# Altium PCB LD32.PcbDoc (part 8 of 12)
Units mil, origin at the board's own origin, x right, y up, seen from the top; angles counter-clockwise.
Board outline 7007.87 x 4368.85 mil, 12 copper layers (Top Layer, Int1 (GND), Int2 (AVDD), Int3 (DVDD), Int4 (GND), Int5 (ST), Int6 (SB), Int8 (AGND), Int7 (AVCC), Int9 (VCCA), Int10 (GND), Bottom Layer), stack 60.136 mil thick; 1165 components, 667 nets, 3910 pads, 2570 vias.
Unrouted connection lines stored in the file: 14.
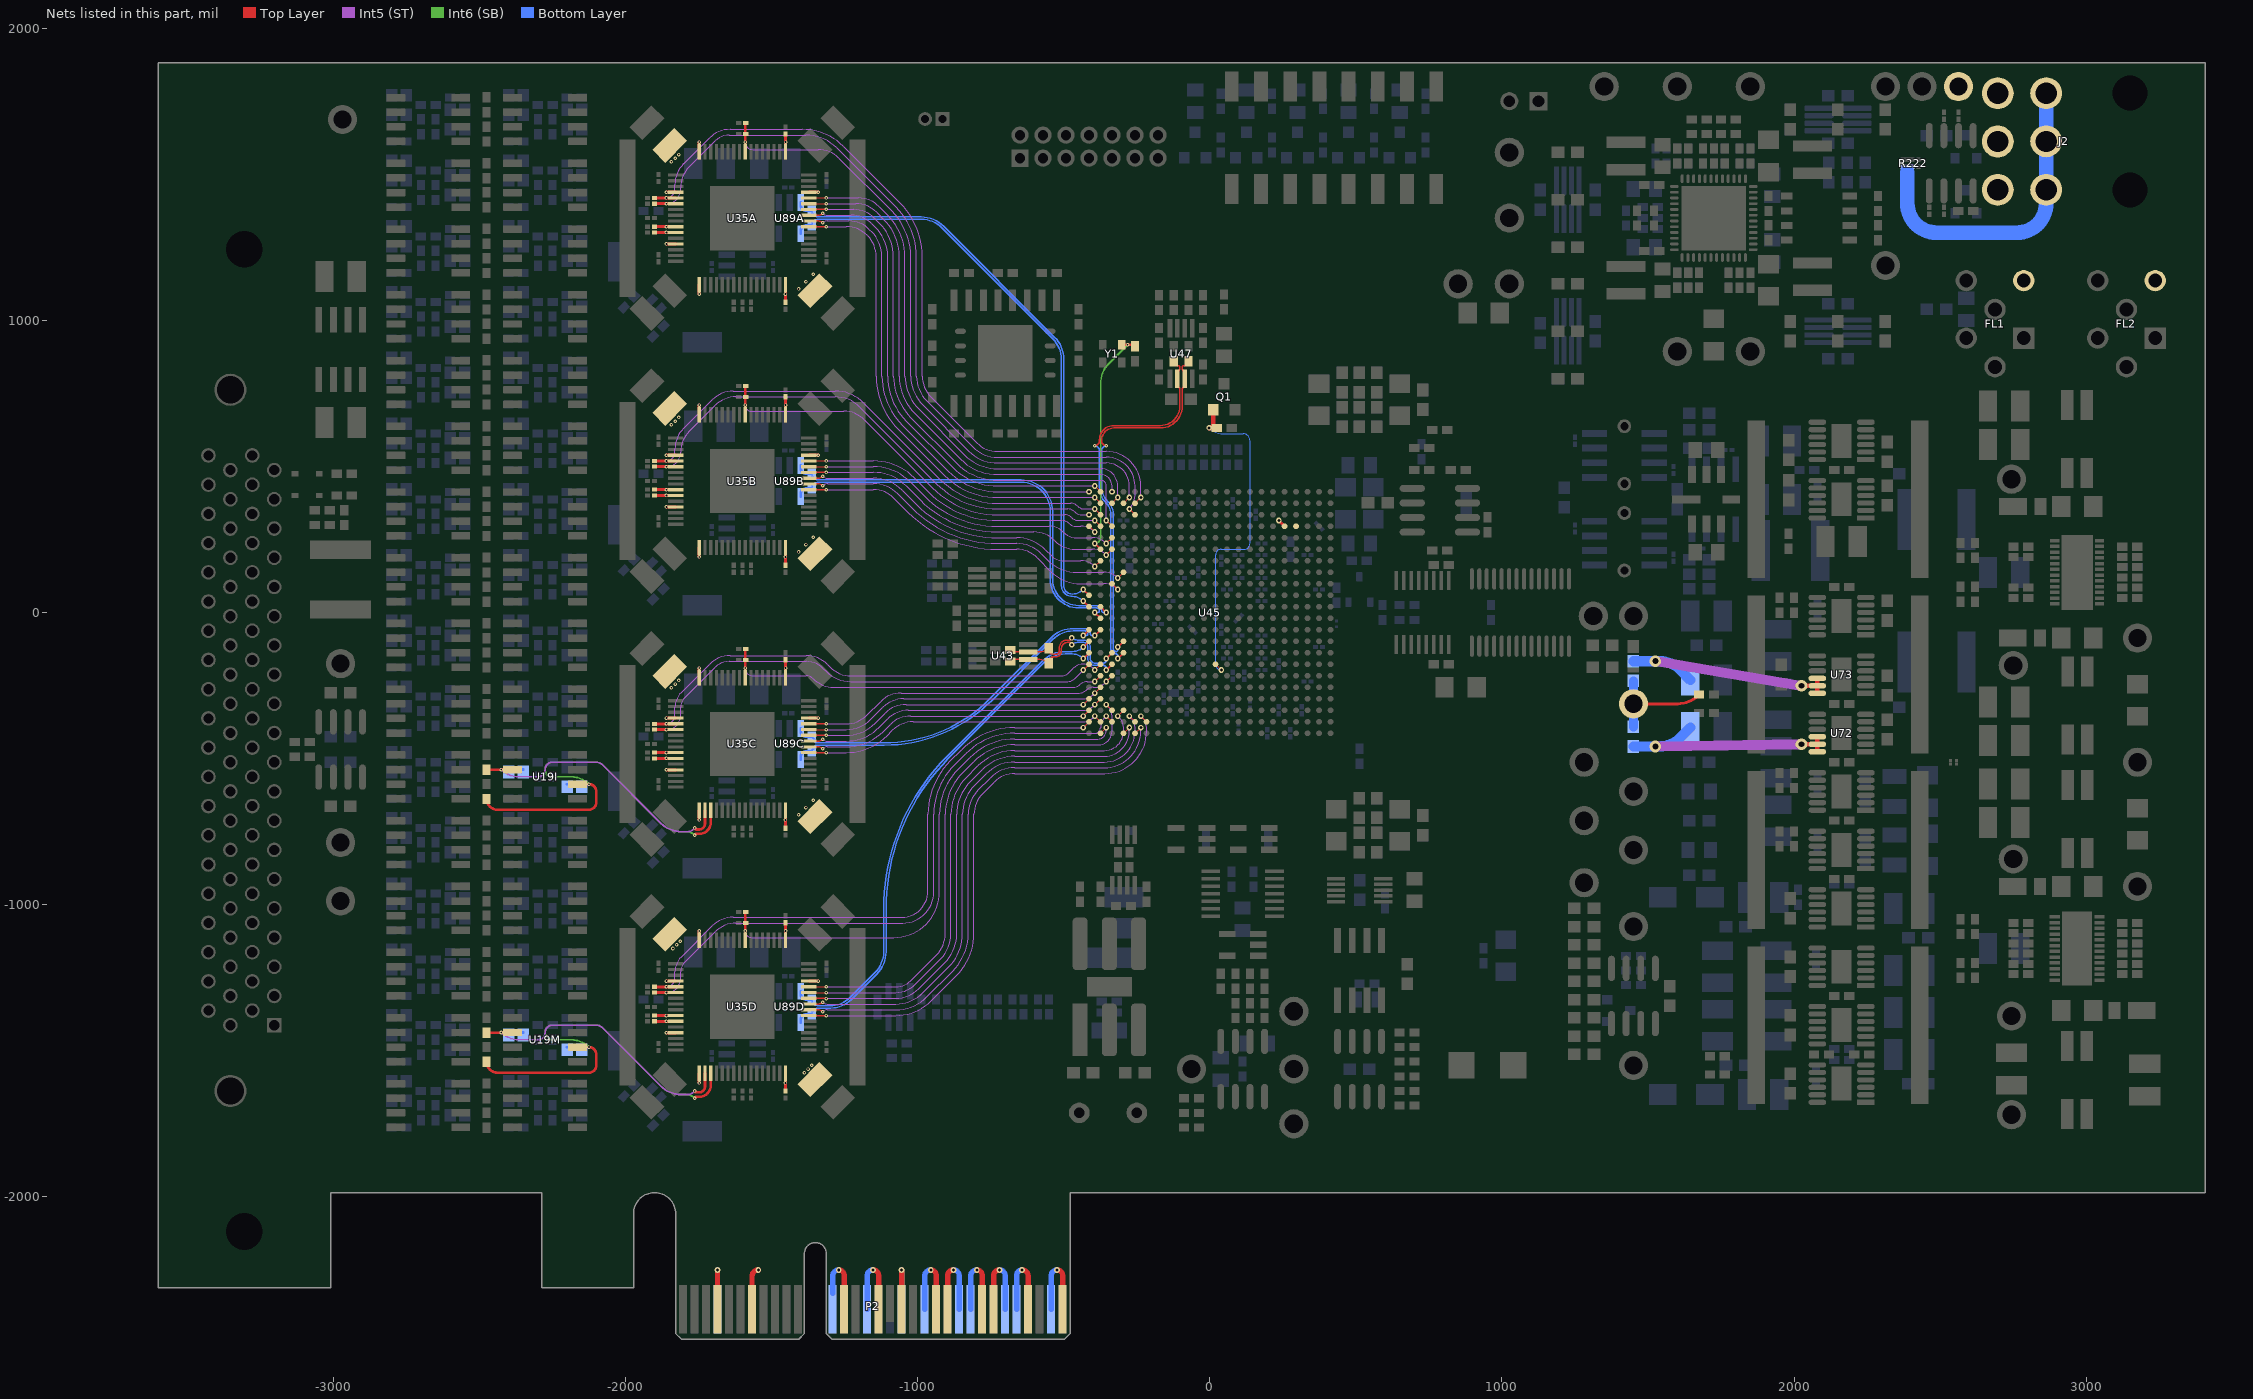
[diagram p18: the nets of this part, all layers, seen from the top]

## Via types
v1: diameter 12, hole 6, Top Layer to Bottom Layer, tented both sides, 1500 vias
v2: diameter 19, hole 10, Top Layer to Bottom Layer, tented both sides, 404 vias
v3: diameter 20, hole 10, Top Layer to Bottom Layer, tented both sides, 337 vias
v4: diameter 14, hole 7, Top Layer to Bottom Layer, tented both sides, 212 vias
v5: diameter 30, hole 15, Top Layer to Bottom Layer, tented both sides, 37 vias
v6: diameter 19.68, hole 7.87, Top Layer to Bottom Layer, 25 vias
v7: diameter 40, hole 20, Top Layer to Bottom Layer, tented both sides, 16 vias
v8: diameter 19.02, hole 10, Top Layer to Bottom Layer, tented both sides, 10 vias
v9: diameter 40, hole 20, Top Layer to Bottom Layer, 9 vias
v10: diameter 60, hole 40, Top Layer to Bottom Layer, 5 vias
v11: diameter 25, hole 13, Top Layer to Bottom Layer, 4 vias
v12: diameter 50, hole 25, Top Layer to Bottom Layer, tented both sides, 4 vias
v13: diameter 35, hole 20, Top Layer to Bottom Layer, 2 vias
v14: diameter 50, hole 25, Top Layer to Bottom Layer, 2 vias
v15: diameter 63, hole 45, Top Layer to Bottom Layer, 1 vias
v16: diameter 14.02, hole 7.01, Top Layer to Bottom Layer, tented both sides, 1 vias
v17: diameter 60, hole 40, Top Layer to Bottom Layer, tented both sides, 1 vias

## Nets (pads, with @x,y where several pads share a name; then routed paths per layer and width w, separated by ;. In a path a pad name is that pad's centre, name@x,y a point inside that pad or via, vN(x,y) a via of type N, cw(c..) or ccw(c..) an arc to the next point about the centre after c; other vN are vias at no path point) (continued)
D8C_N: C319I.2 R7I.2 R335I.1 U19I.6 U35C.35 | length 3191.3
  Top Layer w9: U19I.6@-2163.78,-587.5 v1(-2125,-587.5) ; -2100,-649.92 cw(c-2125,-649.92) -2125,-674.92 -2438.09,-674.92 -2438.09,-675 ; v1(-1762.5,-762.5) cw(c-1757.5,-762.5) -1757.5,-757.5 -1747.5,-757.5 ccw(c-1747.5,-718.27) -1708.27,-718.27 U35C.35@-1708.27,-677.5 ; R7I.2@-2475,-638.09 ccw(c-2438.09,-638.09) -2438.09,-675 ; R7I.2@-2475,-638.09 ccw(c-2438.09,-638.09) -2438.09,-675 ; R7I.2@-2475,-638.09 ccw(c-2438.09,-638.09) -2438.09,-675 ; R7I.2@-2475,-638.09 ccw(c-2438.09,-638.09) -2438.09,-675 ; R7I.2@-2475,-638.09 ccw(c-2438.09,-638.09) -2438.09,-675 ; -2125,-675 ccw(c-2125,-650) -2100,-650 ; -2125,-675 ccw(c-2125,-650) -2100,-650 ; -2125,-675 ccw(c-2125,-650) -2100,-650 ; -2125,-675 ccw(c-2125,-650) -2100,-650 ; -2125,-675 ccw(c-2125,-650) -2100,-650 ; -2125,-675 ccw(c-2125,-650) -2100,-650 ; -2125,-675 ccw(c-2125,-650) -2100,-650 ; -2125,-675 ccw(c-2125,-650) -2100,-650 ; -2125,-675 ccw(c-2125,-650) -2100,-650 ; -2125,-675 ccw(c-2125,-650) -2100,-650 ; -2125,-675 ccw(c-2125,-650) -2100,-650 ; -2125,-675 ccw(c-2125,-650) -2100,-650 ; -2125,-675 ccw(c-2125,-650) -2100,-650 ; -2125,-675 ccw(c-2125,-650) -2100,-650 ; -2125,-675 ccw(c-2125,-650) -2100,-650 ; -2125,-675 ccw(c-2125,-650) -2100,-650 ; -2125,-675 ccw(c-2125,-650) -2100,-650 ; -2125,-675 ccw(c-2125,-650) -2100,-650 ; -2125,-675 ccw(c-2125,-650) -2100,-650 ; -2125,-675 ccw(c-2125,-650) -2100,-650 ; -2125,-675 ccw(c-2125,-650) -2100,-650 ; v1(-2125,-587.5) cw(c-2125,-612.5) -2100,-612.5 ; v1(-2125,-587.5) cw(c-2125,-612.5) -2100,-612.5 ; v1(-2125,-587.5) cw(c-2125,-612.5) -2100,-612.5 ; v1(-2125,-587.5) cw(c-2125,-612.5) -2100,-612.5 ; v1(-2125,-587.5) cw(c-2125,-612.5) -2100,-612.5 ; v1(-2125,-587.5) cw(c-2125,-612.5) -2100,-612.5 ; v1(-2125,-587.5) cw(c-2125,-612.5) -2100,-612.5 ; v1(-2125,-587.5) cw(c-2125,-612.5) -2100,-612.5 ; v1(-2125,-587.5) cw(c-2125,-612.5) -2100,-612.5 ; v1(-2125,-587.5) cw(c-2125,-612.5) -2100,-612.5 ; v1(-2125,-587.5) cw(c-2125,-612.5) -2100,-612.5 ; v1(-2125,-587.5) cw(c-2125,-612.5) -2100,-612.5 ; -2100,-650 -2100,-612.5 ; -2100,-650 -2100,-612.5
  Int6 (SB) w6: v1(-2125,-587.5) ccw(c-2185.36,-647.86) -2185.36,-562.5 -2250,-562.5 cw(c-2250,-537.5) -2275,-537.5 cw(c-2250,-537.5) -2250,-512.5 ; -1792.5,-750 -1792.68,-750 ; v1(-1762.5,-762.5) ccw(c-1792.68,-792.68) -1792.68,-750 ; -2250,-512.5 -2100,-512.5 ; -2250,-512.5 -2100,-512.5 ; -2100,-512.5 cw(c-2100,-542.68) -2078.66,-521.34 -1879.29,-720.71 ccw(c-1808.58,-650) -1808.58,-750 -1792.68,-750
  Bottom Layer w9: R335I.1@-2200,-587.5 v1(-2125,-587.5)
D8C_P: C383I.2 R8I.2 R383I.1 U19I.2 U35C.34 | length 1808.4
  Top Layer w9: R8I.2@-2475,-538.09 v1(-2425,-537.5) U19I.2@-2386.22,-537.5 U19I.2@-2380,-537.5 ; v1(-1762.5,-737.5) ccw(c-1757.5,-737.5) -1757.5,-742.5 -1747.5,-742.5 ccw(c-1747.5,-722.95) -1727.95,-722.95 U35C.34@-1727.95,-677.5
  Int5 (ST) w6: v1(-2425,-537.5) ccw(c-2364.64,-477.14) -2364.64,-562.5 -2300,-562.5 ccw(c-2300,-537.5) -2275,-537.5 cw(c-2250,-537.5) -2250,-512.5 ; v1(-1762.5,-737.5) -1766.16,-741.16 cw(c-1787.5,-719.82) -1787.5,-750 -1808.58,-750 cw(c-1808.58,-650) -1879.29,-720.71 -2078.66,-521.34 ccw(c-2100,-542.68) -2100,-512.5 ; -2250,-512.5 -2100,-512.5 ; -2250,-512.5 -2100,-512.5 ; -2250,-512.5 -2100,-512.5 ; -2250,-512.5 -2100,-512.5 ; -2250,-512.5 -2100,-512.5 ; -2250,-512.5 -2100,-512.5
  Bottom Layer w9: v1(-2425,-537.5) R383I.1@-2350,-537.5
D8D_N: C319M.2 R7M.2 R335M.1 U19M.6 U35D.35 | length 2602.1
  Top Layer w9: U19M.6@-2163.78,-1487.5 v1(-2125,-1487.5) ; v1(-1762.5,-1662.5) cw(c-1757.5,-1662.5) -1757.5,-1657.5 -1747.5,-1657.5 ccw(c-1747.5,-1618.27) -1708.27,-1618.27 U35D.35@-1708.27,-1577.5 ; R7M.2@-2475,-1538.09 ccw(c-2438.09,-1538.09) -2438.09,-1575 ; R7M.2@-2475,-1538.09 ccw(c-2438.09,-1538.09) -2438.09,-1575 ; R7M.2@-2475,-1538.09 ccw(c-2438.09,-1538.09) -2438.09,-1575 ; R7M.2@-2475,-1538.09 ccw(c-2438.09,-1538.09) -2438.09,-1575 ; R7M.2@-2475,-1538.09 ccw(c-2438.09,-1538.09) -2438.09,-1575 ; -2438.09,-1575 -2125,-1575 ; -2125,-1575 ccw(c-2125,-1550) -2100,-1550 ; -2125,-1575 ccw(c-2125,-1550) -2100,-1550 ; -2125,-1575 ccw(c-2125,-1550) -2100,-1550 ; -2125,-1575 ccw(c-2125,-1550) -2100,-1550 ; -2125,-1575 ccw(c-2125,-1550) -2100,-1550 ; -2125,-1575 ccw(c-2125,-1550) -2100,-1550 ; -2125,-1575 ccw(c-2125,-1550) -2100,-1550 ; -2125,-1575 ccw(c-2125,-1550) -2100,-1550 ; -2125,-1575 ccw(c-2125,-1550) -2100,-1550 ; -2125,-1575 ccw(c-2125,-1550) -2100,-1550 ; -2125,-1575 ccw(c-2125,-1550) -2100,-1550 ; -2125,-1575 ccw(c-2125,-1550) -2100,-1550 ; v1(-2125,-1487.5) cw(c-2125,-1512.5) -2100,-1512.5 ; v1(-2125,-1487.5) cw(c-2125,-1512.5) -2100,-1512.5 ; v1(-2125,-1487.5) cw(c-2125,-1512.5) -2100,-1512.5 ; v1(-2125,-1487.5) cw(c-2125,-1512.5) -2100,-1512.5 ; v1(-2125,-1487.5) cw(c-2125,-1512.5) -2100,-1512.5 ; v1(-2125,-1487.5) cw(c-2125,-1512.5) -2100,-1512.5 ; v1(-2125,-1487.5) cw(c-2125,-1512.5) -2100,-1512.5 ; -2100,-1550 -2100,-1512.5 ; -2100,-1550 -2100,-1512.5
  Int6 (SB) w6: v1(-2125,-1487.5) ccw(c-2185.36,-1547.86) -2185.36,-1462.5 -2250,-1462.5 cw(c-2250,-1437.5) -2275,-1437.5 cw(c-2250,-1437.5) -2250,-1412.5 ; -1792.5,-1650 -1792.68,-1650 ; v1(-1762.5,-1662.5) ccw(c-1792.68,-1692.68) -1792.68,-1650 ; -2250,-1412.5 -2100,-1412.5 ; -2250,-1412.5 -2100,-1412.5 ; -2100,-1412.5 cw(c-2100,-1442.68) -2078.66,-1421.34 -1879.29,-1620.71 ccw(c-1808.58,-1550) -1808.58,-1650 -1792.68,-1650
  Bottom Layer w9: R335M.1@-2200,-1487.5 v1(-2125,-1487.5)
D8D_P: C383M.2 R8M.2 R383M.1 U19M.2 U35D.34 | length 1508.4
  Top Layer w9: R8M.2@-2475,-1438.09 v1(-2425,-1437.5) U19M.2@-2386.22,-1437.5 U19M.2@-2380,-1437.5 ; v1(-1762.5,-1637.5) ccw(c-1757.5,-1637.5) -1757.5,-1642.5 -1747.5,-1642.5 ccw(c-1747.5,-1622.95) -1727.95,-1622.95 U35D.34@-1727.95,-1577.5
  Int5 (ST) w6: v1(-2425,-1437.5) ccw(c-2364.64,-1377.14) -2364.64,-1462.5 -2300,-1462.5 ccw(c-2300,-1437.5) -2275,-1437.5 cw(c-2250,-1437.5) -2250,-1412.5 ; v1(-1762.5,-1637.5) -1766.16,-1641.16 cw(c-1787.5,-1619.82) -1787.5,-1650 -1808.58,-1650 cw(c-1808.58,-1550) -1879.29,-1620.71 -2078.66,-1421.34 ccw(c-2100,-1442.68) -2100,-1412.5 ; -2250,-1412.5 -2100,-1412.5 ; -2250,-1412.5 -2100,-1412.5 ; -2250,-1412.5 -2100,-1412.5 ; -2250,-1412.5 -2100,-1412.5
  Bottom Layer w9: v1(-2425,-1437.5) R383M.1@-2350,-1437.5
DAC1.BCLK: U35A.60 U45.AA20 | length 1842.3
  Top Layer w4.2: U35A.60@-1372.5,1418.9 v1(-1312.5,1418.9)
  Top Layer w4.21: U45.AA20@-334.65,374.02 v2(-314.96,393.7)
  Int5 (ST) w4.21: v1(-1312.5,1418.9) -1312.35,1418.75 -1202.87,1418.75 cw(c-1202.87,1318.75) -1132.16,1389.46 -1101.42,1358.73 cw(c-1241.73,1218.42) -1043.31,1218.42 -1043.31,809.14 ccw(c-884.25,809.14) -996.72,696.67 -838.76,538.71 ccw(c-726.3,651.18) -726.3,492.13 -374.02,492.13 cw(c-374.02,433.07) -314.96,433.07 v2(-314.96,393.7)
DAC1.D0: U35A.58 U45.W20 | length 1867.1
  Top Layer w4.21: v2(-354.33,314.96) U45.W20@-334.65,295.28
  Top Layer w5: U35A.58@-1372.5,1379.53 -1372.09,1379.93 -1312.91,1379.93 v1(-1312.5,1380.34)
  Int5 (ST) w4.21: v1(-1312.5,1380.34) -1311.69,1379.53 -1219.32,1379.53 cw(c-1219.32,1279.53) -1148.61,1350.24 -1129.26,1330.89 cw(c-1241.73,1218.42) -1082.68,1218.42 -1082.68,1172.14 ; -1082.68,1181.1 -1082.68,1172.14 ; v2(-354.33,314.96) -354.33,433.07 ccw(c-374.02,433.07) -374.02,452.76 -726.3,452.76 cw(c-726.3,651.18) -866.6,510.87 -1024.56,668.83 cw(c-884.25,809.14) -1082.68,809.14 -1082.68,1172.14
DAC1.D1: U35A.57 U45.AB21 | length 1691.4
  Top Layer w4.21: v2(-393.7,433.07) U45.AB21@-374.02,413.39
  Top Layer w5: U35A.57@-1372.5,1359.84 -1340.47,1359.84 ccw(c-1340.47,1381.72) v1(-1325,1366.25)
  Int5 (ST) w4.21: v1(-1325,1366.25) ccw(c-1309.53,1381.72) -1309.53,1359.84 -1227.48,1359.84 cw(c-1227.48,1259.84) -1156.77,1330.55 -1143.18,1316.97 cw(c-1241.73,1218.42) -1102.36,1218.42 -1102.36,809.14 ccw(c-884.25,809.14) -1038.48,654.91 -880.52,496.95 ccw(c-726.3,651.18) -726.3,433.07 v2(-393.7,433.07)
DAC1.D2: U35A.56 U45.AB22 | length 1643
  Top Layer w5: U35A.56@-1372.5,1340.16 -1340.47,1340.16 cw(c-1340.47,1318.28) v1(-1325,1333.75)
  Int5 (ST) w4.21: v1(-1325,1333.75) cw(c-1309.53,1318.28) -1309.53,1340.16 -1235.63,1340.16 cw(c-1235.63,1240.16) -1164.92,1310.87 -1157.1,1303.05 cw(c-1241.73,1218.42) -1122.05,1218.42 -1122.05,809.14 ccw(c-884.25,809.14) -1052.4,640.99 -894.44,483.03 ccw(c-726.3,651.18) -726.3,413.39 v2(-413.39,413.39)
DAC1.D3: U35A.55 U45.AA21 | length 1686.2
  Top Layer w4.21: v2(-393.7,393.7) U45.AA21@-374.02,374.02
  Top Layer w5: U35A.55@-1372.5,1320.47 v1(-1312.5,1320.47)
  Int5 (ST) w4.21: v1(-1312.5,1320.47) -1243.78,1320.47 cw(c-1243.78,1220.47) -1173.07,1291.18 -1171.02,1289.13 cw(c-1241.73,1218.42) -1141.73,1218.42 -1141.73,809.14 ccw(c-884.25,809.14) -1066.32,627.07 -908.36,469.12 ccw(c-726.3,651.18) -726.3,393.7 v2(-393.7,393.7)
DAC1.DCLK_N: R319A.1 U45.M22 U89A.4 | length 2041.2
  Top Layer w5: v2(-433.07,39.37) U45.M22@-413.39,19.69
  Bottom Layer w5: R319A.1@-1362.5,1324.41 cw(c-1340.91,1324.41) -1340.91,1346 -987.42,1346 cw(c-987.42,1246) -916.71,1316.71 -537.29,937.29 cw(c-608,866.58) -508,866.58 -508,92.12 ccw(c-470.94,92.12) -470.94,55.06 cw(c-470.94,1.5) v2(-433.07,39.37)
  Bottom Layer w9: U89A.4@-1400.1,1296.85 -1400.1,1306.81 cw(c-1382.5,1306.81) -1382.5,1324.41 R319A.1@-1362.5,1324.41
DAC1.DCLK_P: R319A.2 U45.N22 U89A.3 | length 2041.2
  Top Layer w5: v2(-433.07,78.74) U45.N22@-413.39,59.06
  Bottom Layer w5: R319A.2@-1362.5,1375.59 ccw(c-1340.91,1375.59) -1340.91,1354 -987.42,1354 cw(c-987.42,1246) -911.05,1322.37 -531.63,942.95 cw(c-608,866.58) -500,866.58 -500,92.12 ccw(c-470.94,92.12) -470.94,63.06 ccw(c-470.94,116.61) v2(-433.07,78.74)
  Bottom Layer w9: U89A.3@-1400.1,1403.15 -1400.1,1393.19 ccw(c-1382.5,1393.19) -1382.5,1375.59 R319A.2@-1362.5,1375.59
DAC1.GPIO3: R40A.1 U35A.26 | length 64.3
  Top Layer w10: R40A.1@-1891.83,1320.47 v1(-1860,1320.47) U35A.26@-1827.5,1320.47
DAC1.GPIO4: R39A.1 U35A.27 | length 64.3
  Top Layer w10: R39A.1@-1891.83,1300.79 v1(-1860,1300.79) U35A.27@-1827.5,1300.79
DAC1.LRCK: U35A.59 U45.AB20 | length 1775
  Top Layer w4.21: U35A.59@-1372.5,1399.21 v1(-1312.5,1399.21)
  Int5 (ST) w4.21: v1(-1312.5,1399.21) -1211.17,1399.21 cw(c-1211.17,1299.21) -1140.46,1369.92 -1115.34,1344.81 cw(c-1241.73,1218.42) -1062.99,1218.42 -1062.99,1169.15 ; -1062.99,1181.1 -1062.99,1169.15 ; v2(-334.65,413.39) -334.65,433.07 ccw(c-374.02,433.07) -374.02,472.44 -726.3,472.44 cw(c-726.3,651.18) -852.68,524.79 -1010.64,682.75 cw(c-884.25,809.14) -1062.99,809.14 -1062.99,1169.15
DAC1.RST: R55A.2 R56A.1 U35A.8 U45.AA19 | length 2285.1
  Top Layer w4.21: U45.AA19@-295.28,374.02 v2(-275.59,393.7)
  Top Layer w9: U35A.8@-1590.16,1577.5 v1(-1590.16,1610) -1590.16,1611.36 -1590.16,1672.91 cw(c-1588.06,1672.91) R56A.1@-1588.06,1675
  Int5 (ST) w4.21: v1(-1590.16,1610) ccw(c-1564.8,1610) -1564.8,1584.65 -1340.92,1584.65 cw(c-1340.92,1484.65) -1270.21,1555.36 -1087.51,1372.65 cw(c-1241.73,1218.42) -1023.62,1218.42 -1023.62,809.14 ccw(c-884.25,809.14) -982.8,710.59 -824.84,552.63 ccw(c-726.3,651.18) -726.3,511.81 -354.33,511.81 cw(c-354.33,433.07) -275.59,433.07 v2(-275.59,393.7)
DAC1.SCL: R41A.1 U35A.22 U45.Y18 | length 2718.3
  Top Layer w4.21: v2(-275.59,354.33) U45.Y18@-255.91,334.65
  Top Layer w10: R41A.1@-1891.83,1399.21 v1(-1860,1399.21) U35A.22@-1827.5,1399.21
  Int5 (ST) w4.21: v1(-1860,1399.21) ccw(c-1860,1448.19) -1811.02,1448.19 -1811.02,1454.64 cw(c-1711.02,1454.64) -1781.73,1525.35 -1781.5,1525.59 -1692.91,1614.17 cw(c-1645.39,1566.65) -1645.39,1633.86 -1382.68,1633.86 cw(c-1382.68,1484.65) -1277.17,1590.15 -1073.59,1386.57 cw(c-1241.73,1218.42) -1003.94,1218.42 -1003.94,809.14 ccw(c-884.25,809.14) -968.88,724.51 -810.93,566.55 ccw(c-726.3,651.18) -726.3,531.5 -354.33,531.5 cw(c-354.33,433.07) -255.91,433.07 -255.91,401.85 cw(c-323.11,401.85) v2(-275.59,354.33)
DAC1.SDA: R42A.1 U35A.21 U45.AA18 | length 2704.6
  Top Layer w4.21: U45.AA18@-255.91,374.02 v2(-236.22,393.7)
  Top Layer w10: R42A.1@-1891.83,1418.9 v1(-1860,1418.9) U35A.21@-1827.5,1418.9
  Int5 (ST) w4.21: v1(-1860,1418.9) ccw(c-1860,1448.19) -1830.71,1448.19 -1830.71,1464.48 cw(c-1730.71,1464.48) -1801.42,1535.19 -1801.18,1535.43 -1722.44,1614.17 -1712.36,1624.25 cw(c-1641.65,1553.54) -1641.65,1653.54 -1394.91,1653.54 cw(c-1394.91,1455.12) -1254.6,1595.43 -1059.67,1400.49 cw(c-1241.73,1218.42) -984.25,1218.42 -984.25,1181.1 -984.25,809.14 ccw(c-884.25,809.14) -954.96,738.43 -797.01,580.47 ccw(c-726.3,651.18) -726.3,551.18 -354.33,551.18 cw(c-354.33,433.07) -236.22,433.07 v2(-236.22,393.7)
DAC2.BCLK: U35B.60 U45.W22 | length 1078.7
  Top Layer w4.2: U35B.60@-1372.5,518.9 v1(-1312.5,518.9)
  Top Layer w4.21: U45.W22@-413.39,295.28 v2(-393.7,275.59)
  Int5 (ST) w4.21: v1(-1312.5,518.9) -1312.35,518.75 -1151.24,518.75 cw(c-1151.24,321.06) -1011.45,460.85 -964.04,413.44 ccw(c-726.3,651.18) -726.3,314.96 -506.09,314.96 -506.03,314.96 cw(c-506.05,281.36) -482.29,305.12 ccw(c-458.52,328.88) -458.52,295.28 -441.22,295.28 cw(c-441.22,228.07) v2(-393.7,275.59)
DAC2.D0: U35B.58 U45.U20 | length 1128.6
  Top Layer w4.21: v2(-354.33,196.85) U45.U20@-334.65,216.54
  Top Layer w5: U35B.58@-1372.5,479.53 v1(-1312.5,479.53)
  Int5 (ST) w4.21: v1(-1312.5,479.53) -1151.51,479.53 cw(c-1151.51,320.92) -1039.35,433.07 -991.88,385.6 ccw(c-726.3,651.18) -726.3,275.59 -602.23,275.59 -602.11,275.59 cw(c-602.11,176.41) -531.5,246.06 ccw(c-460.21,317.35) -460.21,216.54 ; -460.18,216.54 -401.85,216.54 cw(c-401.85,149.33) v2(-354.33,196.85)
DAC2.D1: U35B.57 U45.T21 | length 1100.8
  Top Layer w4.21: v2(-393.7,157.48) U45.T21@-374.02,177.17
  Top Layer w5: U35B.57@-1372.5,459.84 -1340.47,459.84 ccw(c-1340.47,481.72) v1(-1325,466.25)
  Int5 (ST) w4.21: v1(-1325,466.25) ccw(c-1309.53,481.72) -1309.53,459.84 -1151.57,459.84 cw(c-1151.57,320.77) -1053.23,419.11 -1005.8,371.68 ccw(c-726.3,651.18) -726.3,255.91 -661.5,255.91 cw(c-661.5,116.54) -562.95,215.08 -543.03,195.16 ccw(c-499.58,238.61) -499.58,177.17 -441.22,177.17 cw(c-441.22,109.96) v2(-393.7,157.48)
DAC2.D2: U35B.56 U45.R19 | length 1185.7
  Top Layer w4.21: v2(-314.96,118.11) U45.R19@-295.28,137.8
  Top Layer w5: U35B.56@-1372.5,440.16 -1340.47,440.16 cw(c-1340.47,418.28) v1(-1325,433.75)
  Int5 (ST) w4.21: v1(-1325,433.75) cw(c-1307.63,416.38) -1307.63,440.94 -1152.42,440.94 cw(c-1152.42,321.41) -1067.89,405.93 -1019.72,357.76 ccw(c-726.3,651.18) -726.3,236.22 -661.5,236.22 cw(c-661.5,116.54) -576.87,201.17 -554.32,178.62 ccw(c-455.77,277.17) -455.77,137.8 -362.48,137.8 cw(c-362.48,70.59) v2(-314.96,118.11)
DAC2.D3: U35B.55 U45.P20 | length 1190.6
  Top Layer w4.21: U45.P20@-334.65,98.43 v2(-314.96,78.74)
  Top Layer w5: U35B.55@-1372.5,420.47 v1(-1312.5,420.47)
  Int5 (ST) w4.21: v1(-1312.5,420.47) -1151.69,420.47 cw(c-1151.69,320.47) -1080.98,391.18 -1033.64,343.84 ccw(c-726.3,651.18) -726.3,216.54 -661.5,216.54 cw(c-661.5,116.54) -590.79,187.25 -543.73,140.18 ccw(c-442.91,241) -442.91,98.43 -362.48,98.43 cw(c-362.48,31.22) v2(-314.96,78.74)
DAC2.DCLK_N: R319B.1 U45.L21 U89B.4 | length 1452.5
  Top Layer w5: v2(-393.7,0) U45.L21@-374.02,-19.68
  Bottom Layer w5: R319B.1@-1362.5,424.41 cw(c-1340.91,424.41) -1340.91,446 -645.85,446 cw(c-645.85,346) -545.85,346 -545.85,113.05 ccw(c-448.55,113.05) -448.55,15.75 -387.86,15.75 cw(c-387.86,5.91) -378.02,5.91 cw(c-383.92,5.91) -383.92,0 v2(-393.7,0)
  Bottom Layer w9: U89B.4@-1400.1,396.85 -1400.1,406.81 cw(c-1382.5,406.81) -1382.5,424.41 R319B.1@-1362.5,424.41
DAC2.DCLK_P: R319B.2 U45.M21 U89B.3 | length 1465.1
  Top Layer w5: U45.M21@-374.02,19.69 v2(-354.33,0)
  Bottom Layer w5: R319B.2@-1362.5,475.59 ccw(c-1340.91,475.59) -1340.91,454 -645.85,454 cw(c-645.85,346) -537.85,346 -537.85,113.05 ccw(c-448.55,113.05) -448.55,23.75 -387.86,23.75 cw(c-387.86,5.91) -370.02,5.91 ccw(c-364.11,5.91) -364.11,0 v2(-354.33,0)
  Bottom Layer w9: U89B.3@-1400.1,503.15 -1400.1,493.19 ccw(c-1382.5,493.19) -1382.5,475.59 R319B.2@-1362.5,475.59
DAC2.GPIO3: R40B.1 U35B.26 | length 64.3
  Top Layer w10: R40B.1@-1891.83,420.47 v1(-1860,420.47) U35B.26@-1827.5,420.47
DAC2.GPIO4: R39B.1 U35B.27 | length 64.3
  Top Layer w10: R39B.1@-1891.83,400.79 v1(-1860,400.79) U35B.27@-1827.5,400.79
DAC2.LRCK: U35B.59 U45.V20 | length 1123.3
  Top Layer w4.21: U35B.59@-1372.5,499.21 v1(-1312.5,499.21) ; v2(-354.33,236.22) U45.V20@-334.65,255.91
  Int5 (ST) w4.21: v1(-1312.5,499.21) -1151.45,499.21 cw(c-1151.45,321.06) -1025.47,447.03 -977.96,399.52 ccw(c-726.3,651.18) -726.3,295.28 -549.57,295.28 cw(c-549.49,228.07) -501.91,275.53 ccw(c-454.44,323.11) -454.42,255.91 -401.85,255.91 cw(c-401.85,188.7) v2(-354.33,236.22)
DAC2.RST: R55B.2 R56B.1 U35B.8 U45.W21 | length 1469.1
  Top Layer w4.21: v2(-393.7,314.96) U45.W21@-374.02,295.28
  Top Layer w9: U35B.8@-1590.16,677.5 v1(-1590.16,710) -1590.16,711.36 -1590.16,772.91 cw(c-1588.06,772.91) R56B.1@-1588.06,775
  Int5 (ST) w4.21: v1(-1590.16,710) ccw(c-1569.13,710) -1569.13,688.98 -1253.16,688.98 cw(c-1253.16,588.98) -1182.45,659.69 -950.12,427.36 ccw(c-726.3,651.18) -726.3,334.65 -496.18,334.65 ; -496.14,334.65 cw(c-496.11,301.28) -472.44,324.8 ccw(c-448.58,348.8) -448.55,314.96 ; -448.52,314.96 v2(-393.7,314.96)
DAC2.SCL: R41B.1 U35B.22 U45.Y22 | length 1779.7
  Top Layer w10: R41B.1@-1891.83,499.21 v1(-1860,499.21) U35B.22@-1827.5,499.21
  Int5 (ST) w4.21: v1(-1860,499.21) ccw(c-1860,548.19) -1811.02,548.19 -1811.02,549.21 cw(c-1711.22,549.21) -1781.79,619.78 -1692.91,708.66 ; -1692.68,708.9 cw(c-1621.96,638.19) -1621.96,738.19 -1282.69,738.19 cw(c-1282.69,618.5) -1198.06,703.13 -936.2,441.28 ccw(c-727.25,650.23) -727.28,354.72 -486.34,354.33 cw(c-486.36,320.73) -462.6,344.49 ccw(c-438.84,368.25) -438.89,334.65 ; -438.85,334.65 v2(-413.39,334.65)
DAC2.SDA: R42B.1 U35B.21 U45.Y21 | length 1830
  Top Layer w4.21: v2(-393.7,354.33) U45.Y21@-374.02,334.65
  Top Layer w10: R42B.1@-1891.83,518.9 v1(-1860,518.9) U35B.21@-1827.5,518.9
  Int5 (ST) w4.21: v1(-1860,518.9) ccw(c-1860,548.19) -1830.71,548.19 -1830.71,558.97 cw(c-1730.71,558.97) -1801.42,629.68 -1702.76,728.35 ; -1702.52,728.58 cw(c-1631.81,657.87) -1631.81,757.87 -1282.69,757.87 cw(c-1282.69,618.5) -1184.14,717.05 -922.28,455.2 ccw(c-726.3,651.18) -726.3,374.02 -476.52,374.02 cw(c-476.52,340.41) -452.76,364.17 ccw(c-428.99,387.94) -428.91,354.33 v2(-393.7,354.33)
DAC3.BCLK: U35C.60 U45.F20 | length 1092.5
  Top Layer w4.21: v2(-354.33,-236.22) U45.F20@-334.65,-216.54
  Top Layer w5: U35C.60@-1372.5,-381.1 v1(-1312.5,-381.1)
  Int5 (ST) w4.21: v1(-1312.5,-381.1) -1244.49,-381.1 ccw(c-1244.49,-281.1) -1173.78,-351.81 -1126.85,-304.88 cw(c-1056.14,-375.59) -1056.14,-275.59 -446.99,-275.59 ccw(c-446.99,-241.99) -423.25,-265.77 ; -423.23,-265.75 cw(c-399.47,-289.51) -399.47,-255.91 -393.7,-255.91 ccw(c-393.7,-208.38) -360.11,-242 v2(-354.33,-236.22)
DAC3.D0: U35C.58 U45.D22 | length 1000.7
  Top Layer w4.21: v2(-433.07,-314.96) U45.D22@-413.39,-295.28
  Top Layer w5: U35C.58@-1372.5,-420.47 v1(-1312.5,-420.47)
  Int5 (ST) w4.21: v1(-1312.5,-420.47) -1244.49,-420.47 ccw(c-1244.49,-281.1) -1145.94,-379.65 -1110.54,-344.25 cw(c-1039.83,-414.96) -1039.83,-314.96 v2(-433.07,-314.96)
DAC3.D1: U35C.57 U45.D21 | length 1048.8
  Top Layer w4.21: v2(-393.7,-314.96) U45.D21@-374.02,-295.28
  Top Layer w5: U35C.57@-1372.5,-440.16 -1340.47,-440.16 ccw(c-1340.47,-418.28) v1(-1325,-433.75)
  Int5 (ST) w4.21: v1(-1325,-433.75) ccw(c-1309.53,-418.28) -1309.53,-440.16 -1244.49,-440.16 ccw(c-1244.49,-281.1) -1132.02,-393.57 -1102.39,-363.93 cw(c-1031.67,-434.65) -1031.67,-334.65 -433.07,-334.65 ; v2@-399.48,-320.74 cw(c-433.07,-287.12) -432.97,-334.65 ; v2@-399.47,-320.73 v2(-393.7,-314.96) ; -433.07,-334.65 ccw(c-433.07,-287.12) -432.97,-334.65 ; -433.07,-334.65 -432.97,-334.65
DAC3.D2: U35C.56 U45.C22 | length 1002.4
  Top Layer w4.2: v2(-433.07,-354.33) U45.C22@-413.39,-334.65
  Top Layer w5: U35C.56@-1372.5,-459.84 -1340.47,-459.84 cw(c-1340.47,-481.72) v1(-1325,-466.25)
  Int5 (ST) w4.21: v1(-1325,-466.25) cw(c-1309.53,-481.72) -1309.53,-459.84 -1244.49,-459.84 ccw(c-1244.49,-281.1) -1118.1,-407.49 -1094.23,-383.62 cw(c-1023.52,-454.32) -1023.52,-354.33 v2(-433.07,-354.33)
DAC3.D3: U35C.55 U45.B21 | length 1043.6
  Top Layer w4.21: v2(-393.7,-354.33) U45.B21@-374.02,-374.02
  Top Layer w5: U35C.55@-1372.5,-479.53 v1(-1312.5,-479.53)
  Int5 (ST) w4.21: v1(-1312.5,-479.53) -1244.49,-479.53 ccw(c-1244.49,-281.1) -1104.18,-421.41 ; -1104.18,-421.41 -1086.08,-403.3 cw(c-1015.37,-474.02) -1015.37,-374.02 -433.07,-374.02 ccw(c-433.07,-326.49) -399.47,-360.1 v2(-393.7,-354.33)
DAC3.DCLK_N: R319C.1 U45.K22 U89C.4 | length 1204.5
  Top Layer w5: v2(-433.07,-78.74) U45.K22@-413.39,-59.06
  Bottom Layer w5: R319C.1@-1365.81,-475.59 R319C.1@-1352.66,-462.44 ; R319C.1@-1352.65,-462.43 ccw(c-1356.13,-458.96) -1351.22,-458.96 cw(c-1346.31,-458.96) -1349.78,-455.49 ; -1349.76,-455.46 cw(c-1346.22,-459) -1346.22,-454 -1115.13,-454 ccw(c-1115.13,66.41) -747.14,-301.57 -537.85,-92.28 cw(c-467.14,-162.99) -467.14,-62.99 -427.23,-62.99 cw(c-427.23,-72.83) -417.39,-72.83 cw(c-423.29,-72.83) -423.29,-78.74 v2(-433.07,-78.74)
  Bottom Layer w9: U89C.4@-1400.1,-503.15 -1400.1,-493.19 cw(c-1382.5,-493.19) -1382.5,-475.59 R319C.1@-1362.5,-475.59
DAC3.DCLK_P: R319C.2 U45.K21 U89C.3 | length 1215.3
  Top Layer w5: v2(-393.7,-78.74) U45.K21@-374.02,-59.06
  Bottom Layer w5: R319C.2@-1362.5,-424.41 -1354.98,-431.93 cw(c-1364.04,-441) -1351.22,-441 ccw(c-1346.22,-441) -1349.76,-444.54 ccw(c-1346.22,-441) -1346.22,-446 -1115.13,-446 ccw(c-1115.13,66.41) -752.8,-295.92 -543.5,-86.62 cw(c-467.14,-162.99) -467.14,-54.99 -427.23,-54.99 cw(c-427.23,-72.83) -409.39,-72.83 ccw(c-403.48,-72.83) -403.48,-78.74 v2(-393.7,-78.74)
  Bottom Layer w9: U89C.3@-1400.1,-396.85 -1400.1,-406.81 ccw(c-1382.5,-406.81) -1382.5,-424.41 R319C.2@-1362.5,-424.41
DAC3.GPIO3: R40C.1 U35C.26 | length 64.3
  Top Layer w10: R40C.1@-1891.83,-479.53 v1(-1860,-479.53) U35C.26@-1827.5,-479.53
DAC3.GPIO4: R39C.1 U35C.27 | length 64.3
  Top Layer w10: R39C.1@-1891.83,-499.21 v1(-1860,-499.21) U35C.27@-1827.5,-499.21
DAC3.LRCK: U35C.59 U45.E21 | length 1047
  Top Layer w4.21: U35C.59@-1372.5,-400.79 v1(-1312.5,-400.79) ; v2(-393.7,-275.59) U45.E21@-374.02,-255.91
  Int5 (ST) w4.21: v1(-1312.5,-400.79) -1244.49,-400.79 ccw(c-1244.49,-281.1) -1159.86,-365.73 -1118.69,-324.56 cw(c-1047.98,-395.28) -1047.98,-295.28 -433.07,-295.28 ccw(c-433.07,-247.75) -399.47,-281.36 v2(-393.7,-275.59)
DAC3.RST: R55C.2 R56C.1 U35C.8 U45.F21 | length 1353.9
  Top Layer w4.21: v2(-393.7,-236.22) U45.F21@-374.02,-216.54
  Top Layer w9: U35C.8@-1590.16,-222.5 v1(-1590.16,-190) -1590.16,-188.64 -1590.16,-127.09 cw(c-1588.06,-127.09) R56C.1@-1588.06,-125
  Int5 (ST) w4.21: v1(-1590.16,-190) ccw(c-1563.62,-190) -1563.62,-216.54 -1381.84,-216.54 cw(c-1381.84,-250.95) -1357.5,-226.62 ccw(c-1286.79,-155.91) -1286.79,-255.91 -466.68,-255.91 ccw(c-466.68,-222.3) -442.91,-246.06 cw(c-419.15,-269.82) -419.15,-236.22 v2(-393.7,-236.22)
DAC3.SCL: R41C.1 U35C.22 U45.G22 | length 1680.6
  Top Layer w4.21: v2(-433.07,-196.85) U45.G22@-413.39,-177.17
  Top Layer w10: R41C.1@-1891.83,-400.79 v1(-1860,-400.79) U35C.22@-1827.5,-400.79
  Int5 (ST) w4.21: v1(-1860,-400.79) ccw(c-1860,-351.81) -1811.02,-351.81 -1811.02,-324.8 cw(c-1763.5,-324.8) -1797.11,-291.21 -1692.91,-187.01 cw(c-1645.39,-234.53) -1645.39,-167.32 -1381.84,-167.32 cw(c-1381.84,-250.95) -1322.7,-191.82 -1313.35,-201.17 ccw(c-1228.72,-116.54) -1228.88,-236.22 -486.36,-236.22 ccw(c-486.36,-202.62) -462.62,-226.4 ; -462.6,-226.38 v2(-433.07,-196.85)
DAC3.SDA: R42C.1 U35C.21 U45.G21 | length 1724.2
  Top Layer w4.21: v2(-393.7,-196.85) U45.G21@-374.02,-177.17
  Top Layer w10: R42C.1@-1891.83,-381.1 v1(-1860,-381.1) U35C.21@-1827.5,-381.1
  Int5 (ST) w4.21: v1(-1860,-381.1) ccw(c-1860,-351.81) -1830.71,-351.81 -1830.71,-324.8 cw(c-1759.42,-324.8) -1809.83,-274.4 -1712.36,-176.93 cw(c-1641.65,-247.64) -1641.65,-147.64 -1381.84,-147.64 cw(c-1381.84,-250.95) -1308.78,-177.9 -1299.43,-187.25 ccw(c-1228.72,-116.54) -1228.72,-216.54 -506.05,-216.54 ccw(c-506.05,-182.93) -482.28,-206.69 -466.68,-191.08 cw(c-433.07,-224.69) -433.07,-177.17 cw(c-433.07,-224.69) v2@-399.48,-191.08 ; v2@-399.47,-191.08 v2(-393.7,-196.85)
DAC4.BCLK: U35D.60 U45.C20 | length 1820.7
  Top Layer w4.2: U35D.60@-1372.5,-1281.1 v1(-1312.5,-1281.1)
  Top Layer w4.21: v2(-354.33,-314.96) U45.C20@-334.65,-334.65
  Int5 (ST) w4.21: v1(-1312.5,-1281.1) -1312.35,-1281.25 -1075.3,-1281.25 ccw(c-1075.3,-1208.16) -1023.62,-1259.84 -934.8,-1171.02 ccw(c-1005.51,-1100.31) -905.51,-1100.31 -905.51,-690.72 cw(c-707.82,-690.72) -847.61,-550.94 -807.55,-510.87 cw(c-667.24,-651.18) -667.24,-452.76 -533.46,-452.76 -380.87,-452.76 ccw(c-380.87,-406.53) -334.65,-406.53 -334.65,-354.33 ccw(c-382.17,-354.33) -348.56,-320.73 v2(-354.33,-314.96)
DAC4.D0: U35D.58 U45.A19 | length 1817.9
  Top Layer w4.21: U45.A19@-295.28,-413.39 -275.59,-393.7 v2(-275.59,-393.57)
  Top Layer w5: U35D.58@-1372.5,-1320.47 -1372.16,-1320.81 -1312.84,-1320.81 v1(-1312.5,-1321.15)
  Int5 (ST) w4.21: v1(-1312.5,-1321.15) -1311.82,-1320.47 -1075.3,-1320.47 ccw(c-1075.3,-1208.16) -995.89,-1287.58 -907.14,-1198.83 ccw(c-1005.76,-1100.21) -866.29,-1100.21 -866.29,-690.99 cw(c-707.68,-690.99) -819.83,-578.84 -779.71,-538.71 cw(c-667.24,-651.18) -667.24,-492.13 -533.46,-492.13 -361.19,-492.13 ccw(c-361.19,-406.53) -275.59,-406.53 v2(-275.59,-393.57)
DAC4.D1: U35D.57 U45.B18 | length 1896.9
  Top Layer w4.21: v2(-275.59,-354.33) U45.B18@-255.91,-374.02
  Top Layer w5: U35D.57@-1372.5,-1340.16 -1340.47,-1340.16 ccw(c-1340.47,-1318.28) v1(-1325,-1333.75)
  Int5 (ST) w4.21: v1(-1325,-1333.75) ccw(c-1309.53,-1318.28) -1309.53,-1340.16 -1075.3,-1340.16 ccw(c-1075.3,-1208.16) -981.97,-1301.5 -893.41,-1212.94 ccw(c-1006.42,-1099.94) -846.6,-1099.94 -846.6,-691.05 cw(c-707.53,-691.05) -805.87,-592.71 -765.79,-552.63 cw(c-667.24,-651.18) -667.24,-511.81 -533.46,-511.81 -361.19,-511.81 ccw(c-361.19,-406.53) -255.91,-406.53 -255.91,-393.7 ccw(c-303.43,-393.7) -269.81,-360.11 v2(-275.59,-354.33)
DAC4.D2: U35D.56 U45.A18 | length 1882.3
  Top Layer w4.21: U45.A18@-255.91,-413.39 v2(-236.22,-393.7)
  Top Layer w5: U35D.56@-1372.5,-1359.84 -1340.47,-1359.84 cw(c-1340.47,-1381.72) v1(-1325,-1366.25)
  Int5 (ST) w4.21: v1(-1325,-1366.25) cw(c-1309.53,-1381.72) -1309.53,-1359.84 -1075.3,-1359.84 ccw(c-1075.3,-1208.16) -968.05,-1315.42 -879.68,-1227.05 ccw(c-1007.07,-1099.67) -826.92,-1099.67 -826.92,-691.11 cw(c-707.38,-691.11) -791.91,-606.59 -751.87,-566.55 cw(c-667.24,-651.18) -667.24,-531.5 -533.46,-531.5 -361.19,-531.5 ccw(c-361.19,-406.53) -236.22,-406.53 v2(-236.22,-393.7)
DAC4.D3: U35D.55 U45.B17 | length 1955.8
  Top Layer w4.21: v2(-236.22,-354.33) U45.B17@-216.54,-374.02
  Top Layer w5: U35D.55@-1372.5,-1379.53 v1(-1312.5,-1379.53)
  Int5 (ST) w4.21: v1(-1312.5,-1379.53) -1075.3,-1379.53 ccw(c-1075.3,-1208.16) -954.13,-1329.34 -865.96,-1241.16 ccw(c-1007.72,-1099.4) -807.23,-1099.4 -807.23,-691.17 cw(c-707.23,-691.17) -777.94,-620.46 -737.95,-580.47 cw(c-667.24,-651.18) -667.24,-551.18 -533.46,-551.18 -359.79,-551.18 ccw(c-359.79,-407.93) -216.54,-407.93 -216.54,-393.7 ccw(c-264.06,-393.7) -230.45,-360.1 v2(-236.22,-354.33)
DAC4.DCLK_N: R319D.1 U45.H22 U89D.4 | length 1779.8
  Top Layer w5: v2(-433.07,-157.48) U45.H22@-413.39,-137.8
  Bottom Layer w5: R319D.1@-1361,-1374.09 R319D.1@-1362.5,-1375.59 cw(c-1340.91,-1375.59) -1340.91,-1354 -1297.49,-1354 ccw(c-1297.49,-1254) -1226.78,-1324.71 -1139.77,-1237.7 ccw(c-1216.14,-1161.33) -1108.14,-1161.33 -1108.14,-1015.12 cw(c-379.1,-1015.12) -894.61,-499.61 -566.08,-171.08 cw(c-495.37,-241.8) -495.37,-141.8 -470.94,-141.8 cw(c-470.94,-195.35) v2(-433.07,-157.48)
  Bottom Layer w9: U89D.4@-1400.1,-1403.15 -1400.1,-1393.19 cw(c-1382.5,-1393.19) -1382.5,-1375.59 R319D.1@-1362.5,-1375.59
DAC4.DCLK_P: R319D.2 U45.J22 U89D.3 | length 1779.4
  Top Layer w5: v2(-433.07,-118.11) U45.J22@-413.39,-98.43
  Bottom Layer w5: R319D.2@-1361,-1325.91 R319D.2@-1362.5,-1324.41 ccw(c-1340.91,-1324.41) -1340.91,-1346 -1300.81,-1346 ccw(c-1300.81,-1246) -1230.1,-1316.71 -1145.43,-1232.04 ccw(c-1216.14,-1161.33) -1116.14,-1161.33 -1116.14,-1015.12 cw(c-379.1,-1015.12) -900.27,-493.95 -571.74,-165.43 cw(c-495.37,-241.8) -495.37,-133.8 -470.94,-133.8 ccw(c-470.94,-80.24) v2(-433.07,-118.11)
  Bottom Layer w9: U89D.3@-1400.1,-1296.85 -1400.1,-1306.81 ccw(c-1382.5,-1306.81) -1382.5,-1324.41 R319D.2@-1362.5,-1324.41
DAC4.GPIO3: R40D.1 U35D.26 | length 64.3
  Top Layer w10: R40D.1@-1891.83,-1379.53 v1(-1860,-1379.53) U35D.26@-1827.5,-1379.53
DAC4.GPIO4: R39D.1 U35D.27 | length 64.3
  Top Layer w10: R39D.1@-1891.83,-1399.21 v1(-1860,-1399.21) U35D.27@-1827.5,-1399.21
DAC4.LRCK: U35D.59 U45.C19 | length 1831.7
  Top Layer w4.21: U35D.59@-1372.5,-1300.79 v1(-1312.5,-1300.79) ; v2(-314.96,-354.33) U45.C19@-295.28,-334.65
  Int5 (ST) w4.21: v1(-1312.5,-1300.79) -1075.3,-1300.79 ccw(c-1075.3,-1208.16) -1009.81,-1273.66 -920.99,-1184.84 ccw(c-1005.51,-1100.31) -885.97,-1100.31 -885.97,-690.93 cw(c-707.82,-690.93) -833.8,-564.96 -793.63,-524.79 cw(c-667.24,-651.18) -667.24,-472.44 -533.46,-472.44 -361.19,-472.44 ccw(c-361.19,-406.53) -295.28,-406.53 -295.28,-393.7 ccw(c-342.8,-393.7) v2@-309.18,-360.11 ; v2(-314.96,-354.33) v2@-309.2,-360.09
DAC4.RST: R55D.2 R56D.1 U35D.8 U45.A21 | length 1897.3
  Top Layer w4.21: U45.A21@-374.02,-413.39 v2(-354.33,-393.7)
  Top Layer w9: U35D.8@-1590.16,-1122.5 v1(-1590.16,-1090) -1590.16,-1088.64 -1590.16,-1027.09 cw(c-1588.06,-1027.09) R56D.1@-1588.06,-1025
  Int5 (ST) w4.21: v1(-1590.16,-1090) ccw(c-1567.66,-1090) -1567.66,-1112.5 -1081.63,-1112.5 ccw(c-1081.63,-956.07) -925.2,-956.07 -925.2,-690.66 cw(c-707.97,-690.66) -861.57,-537.06 -821.47,-496.95 cw(c-667.24,-651.18) -667.24,-433.07 -383.86,-433.07 ccw(c-383.86,-403.54) -354.33,-403.54 v2(-354.33,-393.7)
DAC4.SCL: R41D.1 U35D.22 U45.B20 | length 2237.4
  Top Layer w4.21: v2(-354.33,-354.33) U45.B20@-334.65,-374.02
  Top Layer w10: R41D.1@-1891.83,-1300.79 v1(-1860,-1300.79) U35D.22@-1827.5,-1300.79
  Int5 (ST) w4.21: v1(-1860,-1300.79) ccw(c-1860,-1251.81) -1811.02,-1251.81 -1811.02,-1230.31 cw(c-1763.5,-1230.31) -1797.24,-1196.85 ; -1797.1,-1196.71 ccw(c-1763.5,-1230.31) -1797.24,-1196.85 ; v2(-354.33,-354.33) -360.1,-360.09 ccw(c-326.49,-393.7) -374.02,-393.7 cw(c-393.7,-393.7) -393.7,-413.39 -667.24,-413.39 ccw(c-667.24,-651.18) -835.39,-483.03 -875.54,-523.18 ccw(c-708.12,-690.6) -944.88,-690.6 -944.88,-956.07 cw(c-1051.8,-956.07) -1051.8,-1062.99 -1621.96,-1062.99 ccw(c-1621.96,-1162.99) -1692.68,-1092.28 -1797.24,-1196.85
DAC4.SDA: R42D.1 U35D.21 U45.B22 | length 2121.6
  Top Layer w4.21: v2(-433.07,-393.7) U45.B22@-413.39,-374.02
  Top Layer w10: R42D.1@-1891.83,-1281.1 v1(-1860,-1281.1) U35D.21@-1827.5,-1281.1
  Int5 (ST) w4.21: v1(-1860,-1281.1) ccw(c-1860,-1251.81) -1830.71,-1251.81 -1830.71,-1230.31 cw(c-1759.42,-1230.31) -1809.83,-1179.91 -1702.52,-1072.6 cw(c-1631.81,-1143.31) -1631.81,-1043.31 -1055.12,-1043.31 ccw(c-1055.12,-952.76) -964.57,-952.76 -964.57,-690.54 cw(c-708.27,-690.54) -889.5,-509.31 -849.31,-469.11 cw(c-667.24,-651.18) -667.24,-393.7 v2(-433.07,-393.7)
DONE: Q1.1 R107.1 U45.G11 | length 1159.7
  Top Layer w4.2: U45.G11@19.69,-177.17 v2(39.37,-196.85)
  Top Layer w15.98: v2(-2.39,631.76) 11.81,631.76 Q1.1@11.81,693.9
  Bottom Layer w4.2: v2(-2.39,631.76) ccw(c45.67,679.82) 45.67,611.86 114.1,611.86 cw(c114.1,588.17) 137.8,588.17 137.8,236.22 cw(c118.11,236.22) 118.11,216.54 60,216.54 ; v2(39.37,-196.85) cw(c39.37,-177.17) 19.69,-177.17 19.69,196.85 cw(c39.37,196.85) 39.37,216.54 59.06,216.54
DVDD1.2V: C8A.1 C8B.1 C8C.1 C8D.1 C35A.1 C35B.1 C35C.1 C35D.1 C36A.1 C36B.1 C36C.1 C36D.1 C43A.1 C43B.1 C43C.1 C43D.1 R150.1 R276.2 R277.1 TP21.1 U35A.1 U35A.16 U35A.20 U35A.29 U35A.33 U35A.48 U35A.61 U35B.1 U35B.16 U35B.20 U35B.29 U35B.33 U35B.48 U35B.61 U35C.1 U35C.16 U35C.20 U35C.29 U35C.33 U35C.48 U35C.61 U35D.1 U35D.16 U35D.20 U35D.29 U35D.33 U35D.48 U35D.61 | length 1480.8
  Top Layer w10: v1(-1860,-1438.58) U35D.29@-1827.5,-1438.58 ; v1(-1860,-1261.42) U35D.20@-1827.5,-1261.42 ; v1(-1860,-538.58) U35C.29@-1827.5,-538.58 ; v1(-1860,-361.42) U35C.20@-1827.5,-361.42 ; v1(-1860,361.42) U35B.29@-1827.5,361.42 ; v1(-1860,538.58) U35B.20@-1827.5,538.58 ; v1(-1860,1261.42) U35A.29@-1827.5,1261.42 ; v1(-1860,1438.58) U35A.20@-1827.5,1438.58 ; v1(-1747.64,-1610) U35D.33@-1747.64,-1577.5 ; U35D.16@-1747.64,-1122.5 v1(-1747.64,-1090) ; v1(-1747.64,-710) U35C.33@-1747.64,-677.5 ; U35C.16@-1747.64,-222.5 v1(-1747.64,-190) ; v1(-1747.64,190) U35B.33@-1747.64,222.5 ; U35B.16@-1747.64,677.5 v1(-1747.64,710) ; v1(-1747.64,1090) U35A.33@-1747.64,1122.5 ; U35A.16@-1747.64,1577.5 v1(-1747.64,1610) ; C35D.1@-1452.36,-1632.34 U35D.48@-1452.36,-1577.5 ; U35D.1@-1452.36,-1122.5 -1452.36,-1067.66 C36D.1@-1452.21,-1067.5 ; C35C.1@-1452.36,-732.34 U35C.48@-1452.36,-677.5 ; U35C.1@-1452.36,-222.5 -1452.36,-167.66 C36C.1@-1452.21,-167.5 ; C35B.1@-1452.36,167.66 U35B.48@-1452.36,222.5 ; U35B.1@-1452.36,677.5 -1452.36,732.34 C36B.1@-1452.21,732.5 ; C35A.1@-1452.36,1067.66 U35A.48@-1452.36,1122.5 ; U35A.1@-1452.36,1577.5 -1452.36,1632.34 C36A.1@-1452.21,1632.5 ; U35D.61@-1372.5,-1261.42 v1(-1340,-1261.42) ; U35C.61@-1372.5,-361.42 v1(-1340,-361.42) ; U35B.61@-1372.5,538.58 v1(-1340,538.58) ; U35A.61@-1372.5,1438.58 v1(-1340,1438.58) ; TP21.1@1450,-312.5 1601.74,-312.5 ccw(c1601.74,-212.5) 1672.45,-283.21 R150.1@1674.41,-281.25
  Bottom Layer w30: R276.2@1450,-391.54 TP21.1@1450,-312.5 R277.1@1450,-233.46
  other v1: -1452.5,-1610 -1387.5,-1575 -1375,-1562.5 -1362.5,-1550 -1837.5,-1150 -1825,-1137.5 -1812.5,-1125 -1452.21,-1090 -1452.5,-710 -1407.5,-692.5 -1382.5,-667.5 -1357.5,-642.5 -1842.5,-257.5 -1830,-245 -1817.5,-232.5 -1452.21,-190 -1452.5,190 -1407.5,207.5 -1382.5,232.5 -1357.5,257.5 -1842.5,642.5 -1830,655 -1817.5,667.5 -1452.21,710 -1452.5,1090 -1407.5,1107.5 -1382.5,1132.5 -1357.5,1157.5 -1842.5,1542.5 -1830,1555 -1817.5,1567.5 -1452.21,1610
DVDDL1.2V: C167.2 R276.1 U72.10 U72.11 U72.12 | length 823.1
  Top Layer w15: v7(2025,-450.89) U72.11@2079.44,-450.89 ; U72.12@2079.44,-476.48 U72.11@2079.44,-450.89 ; U72.10@2079.44,-425.3 U72.11@2079.44,-450.89
  Int5 (ST) w35: v7(1525,-458.46) v7(2025,-450.89)
  Bottom Layer w35: R276.1@1450,-458.46 v7(1525,-458.46) 1538.75,-458.46 ccw(c1538.75,-358.46) 1609.46,-429.18 C167.2@1644.88,-393.75
DVDDR1.2V: C168.2 R277.2 U73.10 U73.11 U73.12 | length 830.1
  Top Layer w15: v7(2025,-250.89) U73.11@2079.44,-250.89 ; U73.12@2079.44,-276.48 U73.11@2079.44,-250.89 ; U73.10@2079.44,-225.3 U73.11@2079.44,-250.89
  Int5 (ST) w35: v7(1525,-166.54) v7(2025,-250.89)
  Bottom Layer w35: R277.2@1450,-166.54 v7(1525,-166.54) 1538.75,-166.54 cw(c1538.75,-266.54) 1609.46,-195.82 C168.2@1644.88,-231.25
EMCLK_EN: R96.2 U45.U21 Y1.1 | length 800.8
  Top Layer w5: v2(-393.7,236.22) U45.U21@-374.02,216.54
  Top Layer w10: Y1.1@-302.17,916.34 v1(-281.48,916.34) -267.79,916.34 cw(c-267.79,899.54) R96.2@-255.91,911.42
  Int6 (SB) w5: v2(-393.7,236.22) ccw(c-393.7,255.91) -374.02,255.91 -374.02,782.38 cw(c-274.02,782.38) -344.73,853.09 v1(-281.48,916.34)
EXT12V: J2.1 J2.2 J2.3 R222.1 | length 1074.2
  Bottom Layer w50: 2387.5,1507.5 2387.5,1400 ccw(c2487.5,1400) 2487.5,1300 2762.5,1300 ccw(c2762.5,1400) 2862.5,1400 J2.3@2862.5,1446.79 J2.2@2862.5,1612.5 J2.1@2862.5,1777.5
EXT.TRIGout_N: R76.1 R86.1 U43.2 U45.G20 | length 487.2
  Top Layer w5: R76.1@-683.07,-167.32 cw(c-666.44,-183.96) -666.44,-160.43 U43.2@-621.85,-160.43 -582.07,-160.43 cw(c-582.07,-204.12) R86.1@-551.18,-173.23 ccw(c-557.22,-167.19) -548.68,-167.19 cw(c-533.13,-167.19) -533.13,-151.64 -527.5,-151.64 ccw(c-527.5,-131.89) -507.75,-131.89 -507.75,-122.05 cw(c-488.13,-122.05) -488.13,-102.43 -480.25,-102.43 cw(c-480.25,-110.24) v2(-472.44,-110.24) ; v2(-354.33,-196.85) U45.G20@-334.65,-177.17
  Bottom Layer w5: v2(-472.44,-110.24) cw(c-453.43,-129.25) -453.43,-102.36 -433.07,-102.36 cw(c-433.07,-117.98) -417.45,-117.98 -417.45,-157.48 ccw(c-393.76,-157.48) -393.76,-181.17 -364.11,-181.17 cw(c-364.11,-190.94) -354.33,-190.94 v2(-354.33,-196.85)
EXT.TRIGout_P: R77.1 R86.2 U43.3 U45.H20 | length 487.2
  Top Layer w5: R77.1@-683.07,-127.95 ccw(c-666.44,-111.32) -666.44,-134.84 U43.3@-621.85,-134.84 -582.07,-134.84 ccw(c-582.07,-91.16) R86.2@-551.18,-122.05 cw(c-557.22,-128.08) -548.68,-128.08 ccw(c-533.13,-128.08) -533.13,-143.64 -527.5,-143.64 ccw(c-527.5,-131.89) -515.75,-131.89 -515.75,-122.05 cw(c-488.13,-122.05) -488.13,-94.43 -480.25,-94.43 ccw(c-480.25,-86.61) v2(-472.44,-86.61) ; v2(-354.33,-157.48) U45.H20@-334.65,-137.8
  Bottom Layer w5: v2(-472.44,-86.61) ccw(c-453.74,-67.91) -453.74,-94.36 -433.07,-94.36 cw(c-433.07,-117.98) -409.45,-117.98 -409.45,-157.48 ccw(c-393.76,-157.48) -393.76,-173.17 -364.11,-173.17 ccw(c-364.11,-163.39) -354.33,-163.39 v2(-354.33,-157.48)
EXTCLK.CAUX_N: R101.2 U45.H19 U47.6 | length 1332.3
  Top Layer w5: v1(-393.7,570.87) ccw(c-393.7,586.55) -378.02,586.55 -378.02,590.55 cw(c-328.8,590.55) -328.8,639.76 -169.06,639.76 ccw(c-169.06,706.4) -102.43,706.4 -102.43,763.34 ccw(c-112.43,763.34) -105.35,770.41 -105.45,770.41 -108.34,773.3 cw(c-101.37,780.26) -111.22,780.26 U47.6@-111.22,799.41 -111.22,816.42 cw(c-96.21,816.42) U47.6@-106.84,827.02 ; v2(-314.96,-157.48) U45.H19@-295.28,-137.8 ; R101.2@-123.43,860.24 ccw(c-113.92,860.24) -120.64,853.52 -114.55,847.42 ccw(c-108.75,853.22) -108.75,845.02 -107.43,845.02 cw(c-107.43,840.02) -103.89,843.56 cw(c-107.43,840.02) -102.43,840.02 -102.43,836.61 ; U47.6@-106.82,827.04 U47.6@-106.09,827.77 ; U47.6@-105.35,828.41 -105.45,828.41 -106.08,827.78 ccw(c-114.93,836.61) -102.43,836.61 ; -102.43,835.48 -102.43,836.61
  Bottom Layer w5: v1(-393.7,570.87) cw(c-393.7,555.18) -378.02,555.18 -378.02,431.2 ccw(c-297.15,431.2) -354.33,374.02 cw(c-391.98,336.37) -338.74,336.37 -338.74,-123.93 ccw(c-320.87,-123.93) -320.87,-141.8 cw(c-320.87,-147.7) -314.96,-147.7 v2(-314.96,-157.48)
EXTCLK.CAUX_P: R104.2 U45.J19 U47.7 | length 1319.8
  Top Layer w5: v1(-354.33,570.87) cw(c-354.33,586.55) -370.02,586.55 -370.02,590.55 cw(c-328.8,590.55) -328.8,631.76 -169.06,631.76 ccw(c-169.06,706.4) -94.43,706.4 -94.43,763.34 cw(c-84.42,763.34) -91.5,770.41 -91.4,770.41 -88.51,773.3 ccw(c-95.48,780.26) -85.63,780.26 U47.7@-85.63,799.41 -85.63,816.42 ccw(c-100.64,816.42) -90.01,827.02 U47.7@-90.76,827.77 ; v2(-314.96,-118.11) U45.J19@-295.28,-98.43 ; -94.43,835.48 -94.43,836.61 ; U47.7@-91.5,828.41 -91.4,828.41 U47.7@-90.77,827.78 ; R104.2@-73.43,860.24 cw(c-82.93,860.24) -76.21,853.52 -82.3,847.42 cw(c-88.1,853.22) -88.1,845.02 -89.43,845.02 ccw(c-89.43,840.02) -92.96,843.56 ccw(c-89.43,840.02) -94.43,840.02 -94.43,836.61 ; -94.43,836.61 ccw(c-81.92,836.61) U47.7@-90.77,827.78
  Bottom Layer w5: v1(-354.33,570.87) ccw(c-354.33,555.18) -370.02,555.18 -370.02,431.33 ccw(c-296.82,431.33) -348.58,379.58 cw(c-391.65,336.5) -330.74,336.5 -330.74,-123.93 ccw(c-320.87,-123.93) -320.87,-133.8 ccw(c-320.87,-127.89) -314.96,-127.89 v2(-314.96,-118.11)
EXTCLK_1: U45.W5 | length 27.8
  Top Layer w10: v2(236.22,314.96) U45.W5@255.91,295.28
EXTCLK_2: U45.W4
EXTGND: FL1.3 FL2.3 J2.4 J2.5 J2.6 P2.A4 P2.A12 P2.A15 P2.A18 P2.A20 P2.A23 P2.A24 P2.A27 P2.A28 P2.A31 P2.B4 P2.B7 P2.B13 P2.B16 P2.B18 P2.B21 P2.B22 P2.B25 P2.B26 P2.B29 P2.B32 TP30.1 | length 2971.9
  Top Layer w17.91: P2.B4@-1684.65,-2385 v3(-1684.65,-2250) ; P2.B7@-1566.54,-2385 -1566.54,-2271.17 cw(c-1545.36,-2271.17) v3(-1545.36,-2250) ; v3(-1270,-2250) cw(c-1270,-2268.43) -1251.57,-2268.43 P2.B13@-1251.57,-2385 ; v3(-1152.5,-2250) cw(c-1152.5,-2269.04) -1133.46,-2269.04 P2.B16@-1133.46,-2385 ; P2.B18@-1054.72,-2385 v3(-1054.72,-2250) ; v3(-955,-2250) cw(c-955,-2268.38) -936.61,-2268.38 P2.B21@-936.61,-2385 ; P2.B22@-897.24,-2385 -897.24,-2269.74 cw(c-877.5,-2269.74) v3(-877.5,-2250) ; v3(-797.5,-2250) cw(c-797.5,-2268.37) -779.13,-2268.37 P2.B25@-779.13,-2385 ; P2.B26@-739.76,-2385 -739.76,-2269.76 cw(c-720,-2269.76) v3(-720,-2250) ; v3(-642.5,-2250) cw(c-642.5,-2270.85) -621.65,-2270.85 P2.B29@-621.65,-2385 ; v3(-522.5,-2250) cw(c-522.5,-2268.96) -503.54,-2268.96 P2.B32@-503.54,-2385
  Bottom Layer w17.91: P2.A4@-1684.65,-2385 v3(-1684.65,-2250) ; P2.A12@-1290.94,-2330.02 -1290.94,-2270.94 cw(c-1270,-2270.94) v3(-1270,-2250) ; P2.A15@-1172.83,-2385 -1172.83,-2270.33 cw(c-1152.5,-2270.33) v3(-1152.5,-2250) ; P2.A18@-1054.72,-2385 v3(-1054.72,-2250) ; P2.A20@-975.99,-2385 -975.99,-2270.99 cw(c-955,-2270.99) v3(-955,-2250) ; v3(-877.5,-2250) cw(c-877.5,-2269.63) -857.87,-2269.63 P2.A23@-857.87,-2385 ; P2.A24@-818.5,-2385 -818.5,-2271 cw(c-797.5,-2271) v3(-797.5,-2250) ; v3(-720,-2250) cw(c-720,-2269.61) -700.39,-2269.61 P2.A27@-700.39,-2385 ; P2.A28@-661.02,-2385 -661.02,-2268.52 cw(c-642.5,-2268.52) v3(-642.5,-2250) ; P2.A31@-542.91,-2385 -542.91,-2270.41 cw(c-522.5,-2270.41) v3(-522.5,-2250)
